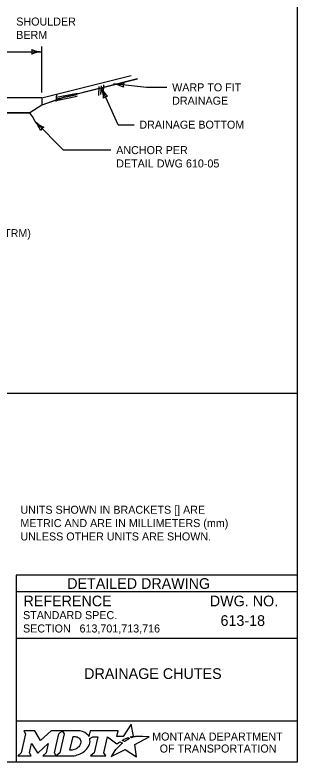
# Model space of a CAD drawing. Extents: x 49991.4 to 50021, y 49987.6 to 50011.4.
# Drawn here: x 50014.64 to 50016.75, y 49987.8 to 49993.4 of the extents above; entities that cross this region are included whole.
import ezdxf

# ---------------------------------------------------------------- set-up
doc = ezdxf.new("R2010")
doc.units = 0
for name, color, linetype in [('Default', 7, 'Continuous'), ('Level 1', 7, 'Continuous'), ('Level 2', 7, 'Continuous'), ('Level 3', 7, 'Continuous'), ('Level 4', 7, 'Continuous'), ('Level 5', 7, 'Continuous')]:
    doc.layers.add(name, color=color, linetype=linetype)

msp = doc.modelspace()

# ---------------------------------------------------------------- linework, layer by layer
at = {"layer": 'Default'}
for points in [[(50015.5126, 49987.9811), (50015.5023, 49987.9867), (50015.5139, 49987.9895), (50015.5255, 49987.9915), (50015.5081, 49988.0816), (50015.4486, 49987.9903), (50015.4013, 49987.9896), (50015.4116, 49988.0337), (50015.2024, 49988.0338), (50015.1923, 49987.9913), (50015.1865, 49987.9996)], [(50014.7056, 49988.0338), (50014.7197, 49988.0104), (50014.6862, 49987.8671), (50014.6605, 49987.8446), (50014.7621, 49987.8446), (50014.7486, 49987.8674), (50014.7648, 49987.9375), (50014.8085, 49987.8685), (50014.8138, 49987.8685), (50014.8889, 49987.938), (50014.8725, 49987.8669), (50014.8478, 49987.8449), (50014.9494, 49987.8449), (50014.9356, 49987.8682), (50014.9688, 49988.0106)], [(50014.9688, 49988.0106), (50014.9941, 49988.0338), (50014.9117, 49988.0338), (50014.8321, 49987.9608), (50014.7876, 49988.0335), (50014.7056, 49988.0338)], [(50015.1077, 49988.0338), (50014.9941, 49988.0338), (50015.0088, 49988.0109), (50014.9749, 49987.8671), (50014.9494, 49987.8449), (50015.06, 49987.8449)], [(50015.1317, 49987.9471), (50015.1305, 49987.939), (50015.1273, 49987.9297), (50015.1231, 49987.9215), (50015.1175, 49987.914), (50015.111, 49987.9071), (50015.1031, 49987.9008), (50015.0948, 49987.8961), (50015.0857, 49987.8922), (50015.0766, 49987.8899), (50015.0674, 49987.889), (50015.0515, 49987.889), (50015.0751, 49987.989), (50015.0911, 49987.989), (50015.0987, 49987.9884), (50015.1063, 49987.9865), (50015.1129, 49987.9835), (50015.119, 49987.9793), (50015.1238, 49987.9743), (50015.1275, 49987.9683), (50015.1302, 49987.9621), (50015.1318, 49987.9547), (50015.1318, 49987.9517), (50015.1317, 49987.9471)], [(50015.3882, 49987.8843), (50015.3729, 49987.8599), (50015.3682, 49987.8524), (50015.3624, 49987.8438), (50015.3601, 49987.8395), (50015.4654, 49987.8926), (50015.5493, 49987.8375), (50015.5362, 49987.9302), (50015.6431, 49987.9886), (50015.5938, 49987.9894), (50015.5637, 49987.9898), (50015.5429, 49987.9901), (50015.5361, 49987.9886), (50015.5312, 49987.9874), (50015.5228, 49987.9851), (50015.5126, 49987.9811)], [(50015.1991, 49987.9747), (50015.2237, 49987.9878), (50015.2606, 49987.9878), (50015.232, 49987.8673), (50015.2045, 49987.8446), (50015.3207, 49987.8446), (50015.3037, 49987.8675), (50015.3319, 49987.9877), (50015.4032, 49987.936), (50015.4243, 49987.9511), (50015.444, 49987.9402)], [(50015.4622, 49987.9535), (50015.4598, 49987.9518), (50015.4415, 49987.9614), (50015.4518, 49987.9671), (50015.4559, 49987.9693), (50015.4645, 49987.9733), (50015.4702, 49987.9759), (50015.4781, 49987.9789), (50015.4854, 49987.9816), (50015.4972, 49987.9742), (50015.4932, 49987.9721), (50015.4886, 49987.9696), (50015.4844, 49987.9674), (50015.4794, 49987.9645), (50015.4775, 49987.9634), (50015.4748, 49987.9618), (50015.4723, 49987.9604), (50015.47, 49987.9588), (50015.4674, 49987.957), (50015.4647, 49987.9552), (50015.4622, 49987.9535)], [(50015.4021, 49987.9004), (50015.4021, 49987.9004)], [(50015.1057, 49987.8522), (50015.1141, 49987.8548), (50015.1271, 49987.8602), (50015.1475, 49987.8712)]]:
    msp.add_lwpolyline(points, dxfattribs=at)
for centre, radius, start, end in [((50015.1308, 49987.9554), 0.0709, 339.5329, 15.8582), ((50015.0868, 49987.9727), 0.1183, 300.9103, 339.1383)]:
    msp.add_arc(centre, radius, start, end, dxfattribs=at)
for centre, major_axis, ratio, start_param, end_param in [((50015.1056, 49987.9864), (0.0834, -0.0037), 0.568097, 0.61298, 1.570796), ((50015.1612, 49987.9937), (0.0361, -0.0295), 0.469099, 1.225588, 1.570796), ((50015.4329, 49987.9305), (-0.0112, -0.0097), 0.021651, 3.157348, 6.283185), ((50015.3952, 49987.8923), (-0.00694, -0.00806), 0.008222, 0, 3.137361), ((50015.4119, 49987.9106), (-0.0098, -0.0102), 0.016458, 3.141593, 6.279097), ((50015.0603, 49987.9932), (0, 0.1484), 0.987302, 3.139398, 3.456847)]:
    msp.add_ellipse(centre, major_axis=major_axis, ratio=ratio, start_param=start_param, end_param=end_param, dxfattribs=at)
at = {"layer": 'Level 1'}
for p, q in [((50014.842, 49992.7741), (50015.5088, 49992.9408)), ((50015.2678, 49992.8581), (50015.2637, 49992.792)), ((50015.2852, 49992.8646), (50015.2811, 49992.7985)), ((50015.3027, 49992.8707), (50015.2986, 49992.8055)), ((50014.9485, 49992.7782), (50015.1073, 49992.8102)), ((50014.842, 49992.7741), (50013.9411, 49992.7741)), ((50014.842, 49992.7741), (50014.842, 49992.7186)), ((50014.9499, 49992.8008), (50014.9465, 49992.7464)), ((50014.947, 49992.7537), (50015.1056, 49992.7857)), ((50014.9477, 49992.7662), (50015.1064, 49992.7981)), ((50014.842, 49992.7186), (50014.7514, 49992.663)), ((50013.8692, 49992.663), (50014.7514, 49992.663)), ((49999.3835, 49990.5622), (50016.7501, 49990.5622))]:
    msp.add_line(p, q, dxfattribs=at)
msp.add_lwpolyline([(49999.3835, 49998.9992), (50016.7501, 49998.9992), (50016.7501, 49987.7988), (49999.3835, 49987.7988)], close=True, dxfattribs=at)
msp.add_lwpolyline([(50015.5568, 49992.9155), (50015.0142, 49992.7795), (50014.842, 49992.7186), (50014.7514, 49992.663), (50013.8692, 49992.663), (50010.8919, 49991.1744), (50010.2132, 49991.2052)], dxfattribs=at)
msp.add_arc((50014.4454, 49992.4392), 0.3791, 24.4752, 36.1728, dxfattribs=at)
at = {"layer": 'Level 3'}
for p, q in [((50014.842, 49992.9687), (50014.842, 49993.1588)), ((50014.4605, 49993.1188), (50014.842, 49993.1188)), ((50014.842, 49992.8974), (50014.842, 49992.9687)), ((50014.842, 49992.8141), (50014.842, 49992.9687)), ((50015.6246, 49992.8525), (50015.3773, 49992.8779)), ((50015.4109, 49992.573), (50015.2867, 49992.8479)), ((50015.7757, 49992.8525), (50015.6246, 49992.8525)), ((50014.7904, 49992.5963), (50015.0025, 49992.3826)), ((50015.4109, 49992.573), (50015.5305, 49992.573)), ((50015.3575, 49992.3826), (50015.0025, 49992.3826))]:
    msp.add_line(p, q, dxfattribs=at)
for centre, radius, start, end in [((50014.8511, 49993.3409), 0.2223, 247.456, 267.6395), ((50014.7137, 49993.1188), 0.0548, 342.1388, 17.8612), ((50014.8535, 49992.8861), 0.233, 92.8273, 112.0772), ((50015.3896, 49993.1105), 0.233, 266.9744, 286.2242), ((50015.3456, 49992.6578), 0.2223, 61.6031, 81.7866), ((50015.5049, 49992.8648), 0.0548, 156.2859, 192.0083), ((50015.0805, 49992.7648), 0.2223, 1.7661, 21.9496), ((50015.494, 49992.9542), 0.233, 207.1374, 226.3872), ((50015.3394, 49992.7311), 0.0548, 96.4489, 132.1713), ((50014.6263, 49992.4463), 0.2223, 22.2398, 42.4233), ((50014.9475, 49992.7684), 0.233, 227.6111, 246.8609), ((50014.8808, 49992.5053), 0.0548, 116.9226, 152.6449)]:
    msp.add_arc(centre, radius, start, end, dxfattribs=at)
at = {"layer": 'Level 4'}
for q in [(50015.5568, 49992.9155), (50014.842, 49992.7186)]:
    msp.add_line((50015.0166, 49992.7804), q, dxfattribs=at)
at = {"layer": 'Level 5'}
for p, q in [((50016.7501, 49989.1988), (50014.6501, 49989.1988)), ((50014.6501, 49989.1988), (50014.6501, 49987.7988)), ((50016.7501, 49989.0738), (50014.6501, 49989.0738)), ((50016.3862, 49988.8587), (50016.3862, 49988.8587)), ((50015.1444, 49988.7993), (50015.1444, 49988.7993)), ((50016.7501, 49988.7238), (50014.6501, 49988.7238)), ((50015.7001, 49988.4747), (50015.7001, 49988.4747)), ((50016.7501, 49988.1057), (50014.6501, 49988.1057))]:
    msp.add_line(p, q, dxfattribs=at)

# ---------------------------------------------------------------- texts
at = {"layer": 'Default'}
for s, p in [('MONTANA DEPARTMENT', (50015.6663, 49987.96)), ('OF TRANSPORTATION', (50015.7225, 49987.87))]:
    msp.add_text(s, height=0.06, dxfattribs=at).set_placement(p)
at = {"layer": 'Level 2'}
for s, height, p in [('SHOULDER', 0.06, (50014.6497, 49993.3154)), ('BERM', 0.06, (50014.6497, 49993.2154)), ('WARP TO FIT', 0.06, (50015.8157, 49992.8226)), ('DRAINAGE', 0.06, (50015.8157, 49992.7226)), ('DRAINAGE BOTTOM', 0.06, (50015.5705, 49992.543)), ('ANCHOR PER', 0.06, (50015.3975, 49992.3526)), ('DETAIL DWG 610-05', 0.06, (50015.3975, 49992.2526)), ('TURF REINFORCEMENT MAT (TRM)', 0.06, (50013.382, 49991.7305)), ('UNITS SHOWN IN BRACKETS [] ARE ', 0.06, (50014.6805, 49989.6588)), ('METRIC AND ARE IN MILLIMETERS (mm) ', 0.06, (50014.6805, 49989.5588)), ('UNLESS OTHER UNITS ARE SHOWN.', 0.06, (50014.6805, 49989.4588)), ('613-18', 0.08, (50016.1778, 49988.8187)), ('613,701,713,716', 0.06, (50015.1229, 49988.7693)), ('DRAINAGE CHUTES', 0.08, (50015.1577, 49988.4214))]:
    msp.add_text(s, height=height, dxfattribs=at).set_placement(p)
at = {"layer": 'Level 5'}
for s, height, p in [('DETAILED DRAWING', 0.0799, (50015.0311, 49989.0963)), ('REFERENCE', 0.08, (50014.7037, 49988.9654)), ('DWG. NO.', 0.08, (50016.0979, 49988.9654)), ('STANDARD SPEC.', 0.06, (50014.7004, 49988.8694)), ('SECTION', 0.06, (50014.7004, 49988.7694))]:
    msp.add_text(s, height=height, dxfattribs=at).set_placement(p)

doc.saveas('drawing.dxf')
